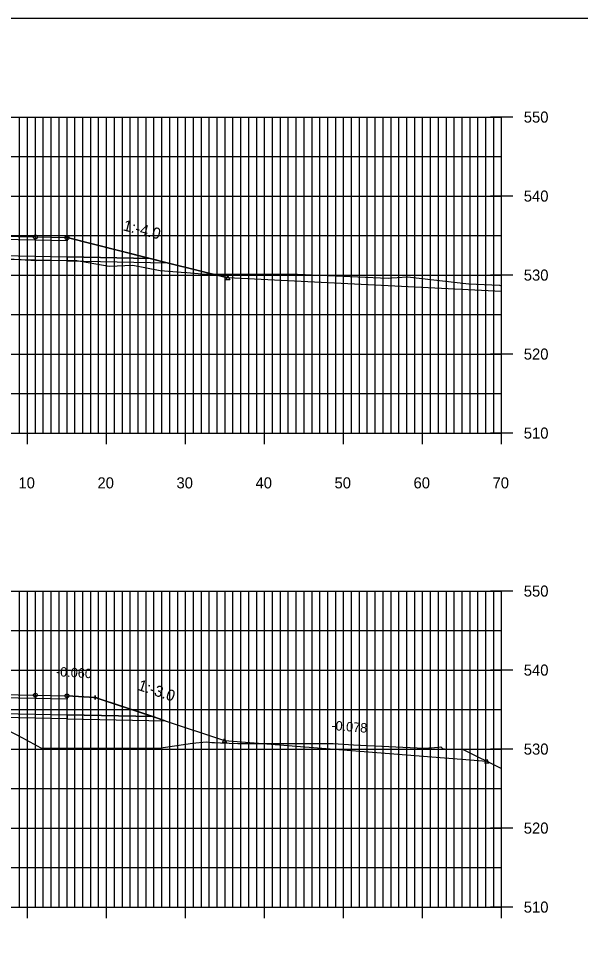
# Model space of a CAD drawing. Extents: x 1509063 to 1512863, y 401160 to 402918.
# Drawn here: x 1511911.6 to 1511982.7, y 402346.1 to 402462.1 of the extents above; entities that cross this region are included whole.
import ezdxf

# ---------------------------------------------------------------- set-up
doc = ezdxf.new("R2010")
doc.units = 0
for name, color, linetype in [('DD_P', 7, 'Continuous'), ('LCUT_P', 7, 'Continuous'), ('NBL1', 7, 'Continuous'), ('PET_P', 7, 'Continuous'), ('PSP_P', 7, 'Continuous'), ('RBS_P', 7, 'Continuous'), ('XAX_P', 7, 'Continuous'), ('XAXTIC_P', 7, 'Continuous'), ('XAXTXT_P_T', 7, 'Continuous'), ('XGL_P', 7, 'Continuous'), ('XSL1_P', 7, 'Continuous'), ('XSL1_P_T', 7, 'Continuous'), ('XSL2_P', 7, 'Continuous'), ('XSL3_P', 7, 'Continuous'), ('XSLOG', 7, 'Continuous')]:
    doc.layers.add(name, color=color, linetype=linetype)

msp = doc.modelspace()

# ---------------------------------------------------------------- linework, layer by layer
at = {"layer": 'DD_P'}
for points in [[(1511917.73, 402434.32), (1511930.41, 402431.15)], [(1511930.16, 402373.15), (1511921.31, 402376.1), (1511917.73, 402376.32)]]:
    msp.add_lwpolyline(points, dxfattribs=at)
for points in [[(1511938.09, 402429.48), (1511938.34, 402428.98), (1511937.84, 402428.98)], [(1511937.67, 402370.9), (1511937.92, 402370.4), (1511937.42, 402370.4)]]:
    msp.add_lwpolyline(points, close=True, dxfattribs=at)
at = {"layer": 'LCUT_P'}
for points in [[(1511972.73, 402427.5), (1511938.09, 402429.23), (1511930.41, 402431.15)], [(1511930.16, 402373.15), (1511937.67, 402370.65), (1511970.85, 402368.05)]]:
    msp.add_lwpolyline(points, dxfattribs=at)
msp.add_lwpolyline([(1511970.85, 402368.3), (1511971.1, 402367.8), (1511970.6, 402367.8)], close=True, dxfattribs=at)
at = {"layer": 'NBL1'}
msp.add_lwpolyline([(1512142.73, 402252.08), (1511822.73, 402252.08), (1511822.73, 402462.08), (1512142.73, 402462.08)], close=True, dxfattribs=at)
at = {"layer": 'PET_P'}
for centre in [(1511913.73, 402434.4), (1511913.73, 402376.4)]:
    msp.add_circle(centre, 0.25, dxfattribs=at)
at = {"layer": 'PSP_P'}
for centre in [(1511917.73, 402434.32), (1511917.73, 402376.32)]:
    msp.add_circle(centre, 0.25, dxfattribs=at)
at = {"layer": 'RBS_P'}
for points in [[(1511902.73, 402434.2), (1511902.73, 402432.2), (1511913.73, 402431.98), (1511917.73, 402431.9), (1511928.24, 402431.69), (1511917.73, 402434.32), (1511917.73, 402433.9), (1511913.73, 402433.98)], [(1511902.73, 402376.2), (1511902.73, 402374.2), (1511913.73, 402373.98), (1511917.73, 402373.9), (1511928.57, 402373.69), (1511921.31, 402376.1), (1511917.73, 402376.32), (1511917.73, 402375.9), (1511913.73, 402375.98)]]:
    msp.add_lwpolyline(points, close=True, dxfattribs=at)
for points in [[(1511917.73, 402434.32), (1511917.73, 402434.57), (1511917.73, 402434.32), (1511917.48, 402434.32), (1511917.73, 402434.32), (1511917.73, 402434.07), (1511917.73, 402434.32), (1511917.98, 402434.32)], [(1511921.31, 402376.1), (1511921.31, 402376.35), (1511921.31, 402376.1), (1511921.06, 402376.1), (1511921.31, 402376.1), (1511921.31, 402375.85), (1511921.31, 402376.1), (1511921.56, 402376.1)]]:
    msp.add_lwpolyline(points, dxfattribs=at)
at = {"layer": 'XAX_P'}
for p, q in [((1511972.73, 402409.58), (1511972.73, 402449.58)), ((1511832.73, 402409.58), (1511972.73, 402409.58)), ((1511972.73, 402349.58), (1511972.73, 402389.58)), ((1511832.73, 402349.58), (1511972.73, 402349.58))]:
    msp.add_line(p, q, dxfattribs=at)
at = {"layer": 'XAXTIC_P'}
for p, q in [((1511974.13, 402449.58), (1511971.33, 402449.58)), ((1511974.13, 402439.58), (1511971.33, 402439.58)), ((1511974.13, 402429.58), (1511971.33, 402429.58)), ((1511974.13, 402419.58), (1511971.33, 402419.58)), ((1511912.73, 402408.18), (1511912.73, 402410.98)), ((1511922.73, 402408.18), (1511922.73, 402410.98)), ((1511932.73, 402408.18), (1511932.73, 402410.98)), ((1511942.73, 402408.18), (1511942.73, 402410.98)), ((1511952.73, 402408.18), (1511952.73, 402410.98)), ((1511962.73, 402408.18), (1511962.73, 402410.98)), ((1511972.73, 402408.18), (1511972.73, 402410.98)), ((1511974.13, 402409.58), (1511971.33, 402409.58)), ((1511974.13, 402389.58), (1511971.33, 402389.58)), ((1511974.13, 402379.58), (1511971.33, 402379.58)), ((1511974.13, 402369.58), (1511971.33, 402369.58)), ((1511974.13, 402359.58), (1511971.33, 402359.58)), ((1511912.73, 402348.18), (1511912.73, 402350.98)), ((1511922.73, 402348.18), (1511922.73, 402350.98)), ((1511932.73, 402348.18), (1511932.73, 402350.98)), ((1511942.73, 402348.18), (1511942.73, 402350.98)), ((1511952.73, 402348.18), (1511952.73, 402350.98)), ((1511962.73, 402348.18), (1511962.73, 402350.98)), ((1511972.73, 402348.18), (1511972.73, 402350.98)), ((1511974.13, 402349.58), (1511971.33, 402349.58))]:
    msp.add_line(p, q, dxfattribs=at)
at = {"layer": 'XGL_P'}
for p, q in [((1511832.73, 402449.58), (1511972.73, 402449.58)), ((1511911.73, 402409.58), (1511911.73, 402449.58)), ((1511912.73, 402409.58), (1511912.73, 402449.58)), ((1511913.73, 402409.58), (1511913.73, 402449.58)), ((1511914.73, 402409.58), (1511914.73, 402449.58)), ((1511915.73, 402409.58), (1511915.73, 402449.58)), ((1511916.73, 402409.58), (1511916.73, 402449.58)), ((1511917.73, 402409.58), (1511917.73, 402449.58)), ((1511918.73, 402409.58), (1511918.73, 402449.58)), ((1511919.73, 402409.58), (1511919.73, 402449.58)), ((1511920.73, 402409.58), (1511920.73, 402449.58)), ((1511921.73, 402409.58), (1511921.73, 402449.58)), ((1511922.73, 402409.58), (1511922.73, 402449.58)), ((1511923.73, 402409.58), (1511923.73, 402449.58)), ((1511924.73, 402409.58), (1511924.73, 402449.58)), ((1511925.73, 402409.58), (1511925.73, 402449.58)), ((1511926.73, 402409.58), (1511926.73, 402449.58)), ((1511927.73, 402409.58), (1511927.73, 402449.58)), ((1511928.73, 402409.58), (1511928.73, 402449.58)), ((1511929.73, 402409.58), (1511929.73, 402449.58)), ((1511930.73, 402409.58), (1511930.73, 402449.58)), ((1511931.73, 402409.58), (1511931.73, 402449.58)), ((1511932.73, 402409.58), (1511932.73, 402449.58)), ((1511933.73, 402409.58), (1511933.73, 402449.58)), ((1511934.73, 402409.58), (1511934.73, 402449.58)), ((1511935.73, 402409.58), (1511935.73, 402449.58)), ((1511936.73, 402409.58), (1511936.73, 402449.58)), ((1511937.73, 402409.58), (1511937.73, 402449.58)), ((1511938.73, 402409.58), (1511938.73, 402449.58)), ((1511939.73, 402409.58), (1511939.73, 402449.58)), ((1511940.73, 402409.58), (1511940.73, 402449.58)), ((1511941.73, 402409.58), (1511941.73, 402449.58)), ((1511942.73, 402409.58), (1511942.73, 402449.58)), ((1511943.73, 402409.58), (1511943.73, 402449.58)), ((1511944.73, 402409.58), (1511944.73, 402449.58)), ((1511945.73, 402409.58), (1511945.73, 402449.58)), ((1511946.73, 402409.58), (1511946.73, 402449.58)), ((1511947.73, 402409.58), (1511947.73, 402449.58)), ((1511948.73, 402409.58), (1511948.73, 402449.58)), ((1511949.73, 402409.58), (1511949.73, 402449.58)), ((1511950.73, 402409.58), (1511950.73, 402449.58)), ((1511951.73, 402409.58), (1511951.73, 402449.58)), ((1511952.73, 402409.58), (1511952.73, 402449.58)), ((1511953.73, 402409.58), (1511953.73, 402449.58)), ((1511954.73, 402409.58), (1511954.73, 402449.58)), ((1511955.73, 402409.58), (1511955.73, 402449.58)), ((1511956.73, 402409.58), (1511956.73, 402449.58)), ((1511957.73, 402409.58), (1511957.73, 402449.58)), ((1511958.73, 402409.58), (1511958.73, 402449.58)), ((1511959.73, 402409.58), (1511959.73, 402449.58)), ((1511960.73, 402409.58), (1511960.73, 402449.58)), ((1511961.73, 402409.58), (1511961.73, 402449.58)), ((1511962.73, 402409.58), (1511962.73, 402449.58)), ((1511963.73, 402409.58), (1511963.73, 402449.58)), ((1511964.73, 402409.58), (1511964.73, 402449.58)), ((1511965.73, 402409.58), (1511965.73, 402449.58)), ((1511966.73, 402409.58), (1511966.73, 402449.58)), ((1511967.73, 402409.58), (1511967.73, 402449.58)), ((1511968.73, 402409.58), (1511968.73, 402449.58)), ((1511969.73, 402409.58), (1511969.73, 402449.58)), ((1511970.73, 402409.58), (1511970.73, 402449.58)), ((1511971.73, 402409.58), (1511971.73, 402449.58)), ((1511972.73, 402409.58), (1511972.73, 402449.58)), ((1511832.73, 402444.58), (1511972.73, 402444.58)), ((1511832.73, 402439.58), (1511972.73, 402439.58)), ((1511832.73, 402434.58), (1511972.73, 402434.58)), ((1511832.73, 402429.58), (1511972.73, 402429.58)), ((1511832.73, 402424.58), (1511972.73, 402424.58)), ((1511832.73, 402419.58), (1511972.73, 402419.58)), ((1511832.73, 402414.58), (1511972.73, 402414.58)), ((1511832.73, 402409.58), (1511972.73, 402409.58)), ((1511832.73, 402389.58), (1511972.73, 402389.58)), ((1511911.73, 402349.58), (1511911.73, 402389.58)), ((1511912.73, 402349.58), (1511912.73, 402389.58)), ((1511913.73, 402349.58), (1511913.73, 402389.58)), ((1511914.73, 402349.58), (1511914.73, 402389.58)), ((1511915.73, 402349.58), (1511915.73, 402389.58)), ((1511916.73, 402349.58), (1511916.73, 402389.58)), ((1511917.73, 402349.58), (1511917.73, 402389.58)), ((1511918.73, 402349.58), (1511918.73, 402389.58)), ((1511919.73, 402349.58), (1511919.73, 402389.58)), ((1511920.73, 402349.58), (1511920.73, 402389.58)), ((1511921.73, 402349.58), (1511921.73, 402389.58)), ((1511922.73, 402349.58), (1511922.73, 402389.58)), ((1511923.73, 402349.58), (1511923.73, 402389.58)), ((1511924.73, 402349.58), (1511924.73, 402389.58)), ((1511925.73, 402349.58), (1511925.73, 402389.58)), ((1511926.73, 402349.58), (1511926.73, 402389.58)), ((1511927.73, 402349.58), (1511927.73, 402389.58)), ((1511928.73, 402349.58), (1511928.73, 402389.58)), ((1511929.73, 402349.58), (1511929.73, 402389.58)), ((1511930.73, 402349.58), (1511930.73, 402389.58)), ((1511931.73, 402349.58), (1511931.73, 402389.58)), ((1511932.73, 402349.58), (1511932.73, 402389.58)), ((1511933.73, 402349.58), (1511933.73, 402389.58)), ((1511934.73, 402349.58), (1511934.73, 402389.58)), ((1511935.73, 402349.58), (1511935.73, 402389.58)), ((1511936.73, 402349.58), (1511936.73, 402389.58)), ((1511937.73, 402349.58), (1511937.73, 402389.58)), ((1511938.73, 402349.58), (1511938.73, 402389.58)), ((1511939.73, 402349.58), (1511939.73, 402389.58)), ((1511940.73, 402349.58), (1511940.73, 402389.58)), ((1511941.73, 402349.58), (1511941.73, 402389.58)), ((1511942.73, 402349.58), (1511942.73, 402389.58)), ((1511943.73, 402349.58), (1511943.73, 402389.58)), ((1511944.73, 402349.58), (1511944.73, 402389.58)), ((1511945.73, 402349.58), (1511945.73, 402389.58)), ((1511946.73, 402349.58), (1511946.73, 402389.58)), ((1511947.73, 402349.58), (1511947.73, 402389.58)), ((1511948.73, 402349.58), (1511948.73, 402389.58)), ((1511949.73, 402349.58), (1511949.73, 402389.58)), ((1511950.73, 402349.58), (1511950.73, 402389.58)), ((1511951.73, 402349.58), (1511951.73, 402389.58)), ((1511952.73, 402349.58), (1511952.73, 402389.58)), ((1511953.73, 402349.58), (1511953.73, 402389.58)), ((1511954.73, 402349.58), (1511954.73, 402389.58)), ((1511955.73, 402349.58), (1511955.73, 402389.58)), ((1511956.73, 402349.58), (1511956.73, 402389.58)), ((1511957.73, 402349.58), (1511957.73, 402389.58)), ((1511958.73, 402349.58), (1511958.73, 402389.58)), ((1511959.73, 402349.58), (1511959.73, 402389.58)), ((1511960.73, 402349.58), (1511960.73, 402389.58)), ((1511961.73, 402349.58), (1511961.73, 402389.58)), ((1511962.73, 402349.58), (1511962.73, 402389.58)), ((1511963.73, 402349.58), (1511963.73, 402389.58)), ((1511964.73, 402349.58), (1511964.73, 402389.58)), ((1511965.73, 402349.58), (1511965.73, 402389.58)), ((1511966.73, 402349.58), (1511966.73, 402389.58)), ((1511967.73, 402349.58), (1511967.73, 402389.58)), ((1511968.73, 402349.58), (1511968.73, 402389.58)), ((1511969.73, 402349.58), (1511969.73, 402389.58)), ((1511970.73, 402349.58), (1511970.73, 402389.58)), ((1511971.73, 402349.58), (1511971.73, 402389.58)), ((1511972.73, 402349.58), (1511972.73, 402389.58)), ((1511832.73, 402384.58), (1511972.73, 402384.58)), ((1511832.73, 402379.58), (1511972.73, 402379.58)), ((1511832.73, 402374.58), (1511972.73, 402374.58)), ((1511832.73, 402369.58), (1511972.73, 402369.58)), ((1511832.73, 402364.58), (1511972.73, 402364.58)), ((1511832.73, 402359.58), (1511972.73, 402359.58)), ((1511832.73, 402354.58), (1511972.73, 402354.58)), ((1511832.73, 402349.58), (1511972.73, 402349.58))]:
    msp.add_line(p, q, dxfattribs=at)
at = {"layer": 'XSL1_P'}
for points in [[(1511864.84, 402433.25), (1511870.2, 402430.57), (1511872.24, 402431.59), (1511878.65, 402434.8), (1511882.23, 402435.01), (1511887.23, 402434.91), (1511887.63, 402434.9), (1511887.73, 402434.32), (1511891.73, 402434.4), (1511902.73, 402434.62), (1511913.73, 402434.4), (1511917.73, 402434.32), (1511928.24, 402431.69), (1511930.41, 402431.15), (1511938.09, 402429.23)], [(1511869.55, 402372.9), (1511870.2, 402372.57), (1511872.24, 402373.59), (1511878.65, 402376.8), (1511882.23, 402377.01), (1511887.23, 402376.91), (1511887.63, 402376.9), (1511887.73, 402376.32), (1511891.73, 402376.4), (1511902.73, 402376.62), (1511913.73, 402376.4), (1511917.73, 402376.32), (1511921.31, 402376.1), (1511928.56, 402373.69), (1511930.16, 402373.15), (1511937.67, 402370.65), (1511970.85, 402368.05)]]:
    msp.add_lwpolyline(points, dxfattribs=at)
at = {"layer": 'XSL2_P'}
for points in [[(1511913.73, 402431.48), (1511902.73, 402431.7), (1511891.73, 402431.48), (1511887.8, 402431.4), (1511887.8, 402431.9), (1511891.73, 402431.98), (1511902.73, 402432.2), (1511913.73, 402431.98), (1511917.73, 402431.9), (1511917.73, 402431.4)], [(1511917.73, 402431.9), (1511917.73, 402431.4), (1511930.41, 402431.15), (1511928.24, 402431.69)], [(1511913.73, 402373.48), (1511902.73, 402373.7), (1511891.73, 402373.48), (1511887.8, 402373.4), (1511887.8, 402373.9), (1511891.73, 402373.98), (1511902.73, 402374.2), (1511913.73, 402373.98), (1511917.73, 402373.9), (1511917.73, 402373.4)], [(1511917.73, 402373.9), (1511917.73, 402373.4), (1511930.16, 402373.15), (1511928.57, 402373.69)]]:
    msp.add_lwpolyline(points, close=True, dxfattribs=at)
for points in [[(1511928.24, 402431.69), (1511917.73, 402431.9)], [(1511928.57, 402373.69), (1511917.73, 402373.9)]]:
    msp.add_lwpolyline(points, dxfattribs=at)
at = {"layer": 'XSL3_P'}
for points in [[(1511891.73, 402433.98), (1511887.8, 402433.9), (1511887.73, 402434.32), (1511891.73, 402434.4), (1511902.73, 402434.62), (1511913.73, 402434.4), (1511917.73, 402434.32), (1511917.73, 402433.9), (1511913.73, 402433.98), (1511902.73, 402434.2)], [(1511891.73, 402375.98), (1511887.8, 402375.9), (1511887.73, 402376.32), (1511891.73, 402376.4), (1511902.73, 402376.62), (1511913.73, 402376.4), (1511917.73, 402376.32), (1511917.73, 402375.9), (1511913.73, 402375.98), (1511902.73, 402376.2)]]:
    msp.add_lwpolyline(points, close=True, dxfattribs=at)
at = {"layer": 'XSLOG'}
for points in [[(1511889.51, 402432.91), (1511913.83, 402431.43), (1511918.73, 402431.48), (1511923.05, 402430.71), (1511926.06, 402430.82), (1511929.5, 402430.17), (1511932.19, 402429.96), (1511932.9, 402429.89), (1511934.31, 402429.77), (1511934.61, 402429.75), (1511944.23, 402429.7), (1511946.91, 402429.69), (1511954.51, 402429.35), (1511958.35, 402429.18), (1511958.82, 402429.22), (1511959.49, 402429.29), (1511960.81, 402429.35), (1511968.56, 402428.49), (1511972.44, 402428.29), (1511972.73, 402428.2)], [(1511909.99, 402372.09), (1511912.09, 402371.01), (1511914.43, 402369.74), (1511923.74, 402369.69), (1511929.36, 402369.71), (1511933.62, 402370.32), (1511935.33, 402370.48), (1511936.07, 402370.43), (1511936.37, 402370.41), (1511937.16, 402370.38), (1511939.35, 402370.29), (1511942.9, 402370.28), (1511951.4, 402370.27), (1511953.96, 402370.14), (1511962.92, 402369.71), (1511963.5, 402369.74), (1511963.86, 402369.76), (1511965.05, 402369.85), (1511965.25, 402369.66), (1511965.49, 402369.62), (1511967.84, 402369.51), (1511972.73, 402367.14)]]:
    msp.add_lwpolyline(points, dxfattribs=at)

# ---------------------------------------------------------------- texts
at = {"layer": 'XAXTXT_P_T'}
for s, p in [('550', (1511975.53, 402448.88)), ('540', (1511975.53, 402438.88)), ('530', (1511975.53, 402428.88)), ('520', (1511975.53, 402418.88)), ('510', (1511975.53, 402408.88)), ('10', (1511911.58, 402402.58)), ('20', (1511921.58, 402402.58)), ('30', (1511931.58, 402402.58)), ('40', (1511941.58, 402402.58)), ('50', (1511951.58, 402402.58)), ('60', (1511961.58, 402402.58)), ('70', (1511971.58, 402402.58)), ('550', (1511975.53, 402388.88)), ('540', (1511975.53, 402378.88)), ('530', (1511975.53, 402368.88)), ('520', (1511975.53, 402358.88)), ('510', (1511975.53, 402348.88))]:
    msp.add_text(s, height=1.4, dxfattribs=at).set_placement(p)
at = {"layer": 'XSL1_P_T'}
for s, height, rotation, p in [('1:-4.0', 1.4, 345.9638, (1511924.73, 402435.25)), ('1:-4.0', 1.4, 345.9638, (1511924.73, 402435.25)), ('1:-4.0', 1.4, 345.9638, (1511924.73, 402435.25)), ('-0.060', 1.2, 356.5664, (1511916.3, 402378.81)), ('1:-3.0', 1.4, 341.5651, (1511926.58, 402377.09)), ('1:-3.0', 1.4, 341.5651, (1511926.58, 402377.09)), ('1:-3.0', 1.4, 341.5651, (1511926.58, 402377.09)), ('-0.078', 1.2, 355.5168, (1511951.14, 402372)), ('-0.078', 1.2, 355.5168, (1511951.14, 402372)), ('-0.078', 1.2, 355.5168, (1511951.14, 402372))]:
    msp.add_text(s, height=height, rotation=rotation, dxfattribs=at).set_placement(p)

doc.saveas('drawing.dxf')
